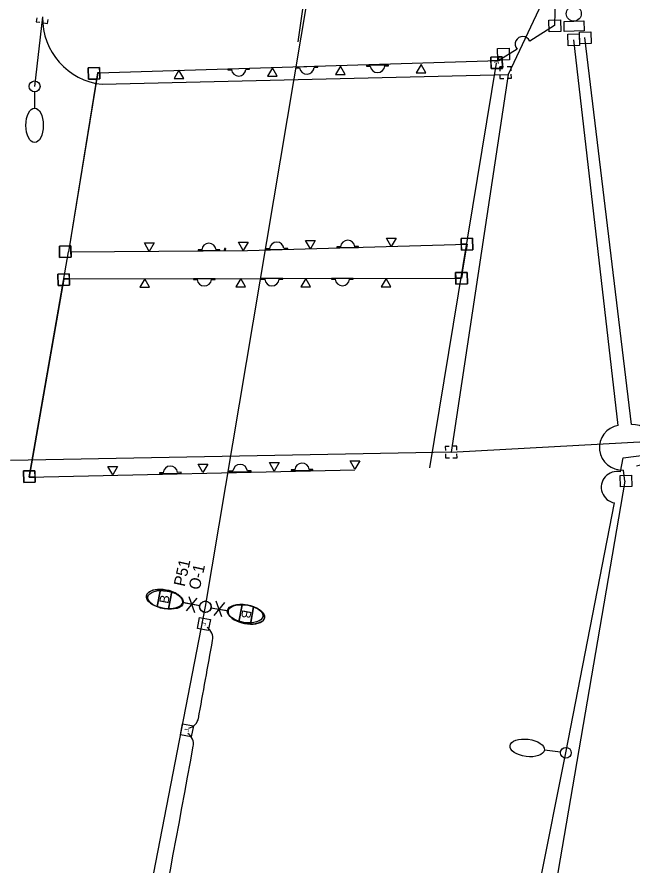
# Model space of a CAD drawing. Extents: x 925407 to 930994, y 604905 to 637063.
# Drawn here: x 930469.3 to 930738.1, y 618416 to 618786.5 of the extents above; entities that cross this region are included whole.
import ezdxf

# ---------------------------------------------------------------- set-up
doc = ezdxf.new("R2010")
doc.units = 0
for name, color, linetype in [('ActivePointCell_dp', 7, 'Continuous'), ('Conduit', 7, 'Continuous'), ('ConduitDB', 7, 'Continuous'), ('ConduitJB', 7, 'Continuous'), ('ConduitOT', 7, 'Continuous'), ('LightingMisc', 7, 'Continuous'), ('LiteCond_ep', 7, 'Continuous'), ('LoadCenter', 7, 'Continuous'), ('Miscellaneous2', 7, 'Continuous'), ('Miscellaneous9', 7, 'Continuous'), ('PoleLight', 7, 'Continuous'), ('PoleLight_ep', 7, 'Continuous'), ('PullBox', 7, 'Continuous'), ('SoilBoxes_px', 7, 'Continuous')]:
    doc.layers.add(name, color=color, linetype=linetype)

msp = doc.modelspace()

# ---------------------------------------------------------------- linework, layer by layer
for points in [[(930560.46, 618685.29), (930560.02, 618685.33), (930559.93, 618684.52), (930560.37, 618684.47)], [(930560.37, 618684.47), (930560.46, 618685.29), (930560.46, 618685.29), (930560.37, 618684.47)]]:
    msp.add_lwpolyline(points, close=True)
at = {"layer": 'ActivePointCell_dp'}
msp.add_line((930618.39, 618963.87), (930592.1, 618775.67), dxfattribs=at)
at = {"layer": 'Conduit'}
for p, q in [((930720.15, 618838.16), (930683.96, 618761.37)), ((930480.53, 618786.47), (930477.05, 618756.15)), ((930506.57, 618757.04), (930683.96, 618761.37)), ((930683.96, 618761.37), (930659.01, 618596.36)), ((930659.01, 618596.36), (930827.84, 618605.52)), ((930734.26, 618593.79), (930822.57, 618605.19)), ((930659.01, 618596.36), (930466.5, 618592.68)), ((930733.07, 618587.68), (930734.26, 618593.79)), ((930709.17, 618464.99), (930730.45, 618574.22)), ((930671.82, 618277.75), (930709.17, 618464.96))]:
    msp.add_line(p, q, dxfattribs=at)
for centre, radius, start, end in [((930509.6, 618785.96), 29.08, 178.9945, 264.0152), ((930731.51, 618581), 6.87, 76.85, 261.1041)]:
    msp.add_arc(centre, radius, start, end, dxfattribs=at)
at = {"layer": 'ConduitDB'}
for p, q in [((930737.86, 618608.37), (930717.5, 618777.55)), ((930732.07, 618608.04), (930712.58, 618776.48)), ((930734.88, 618583.7), (930734.32, 618588.54))]:
    msp.add_line(p, q, dxfattribs=at)
for centre, radius, start, end in [((930733.68, 618598.35), 9.83, 99.4413, 273.7548), ((930738.6, 618599.34), 9.06, 279.0871, 94.6401)]:
    msp.add_arc(centre, radius, start, end, dxfattribs=at)
at = {"layer": 'ConduitJB'}
for p, q in [((930504.59, 618762.1), (930679.89, 618767.39)), ((930679.64, 618767.67), (930680.88, 618767.71)), ((930492.01, 618683.91), (930504.59, 618762.1)), ((930492.54, 618683.83), (930570.06, 618684.49)), ((930570.13, 618684.45), (930665.97, 618687.21)), ((930663.56, 618672.32), (930665.97, 618687.21)), ((930489.8, 618672), (930474.65, 618585.35)), ((930489.8, 618672), (930663.56, 618672.32)), ((930474.65, 618585.35), (930617, 618588.64))]:
    msp.add_line(p, q, dxfattribs=at)
at = {"layer": 'ConduitOT'}
for p, q in [((930704.72, 618801.33), (930704.15, 618782.79)), ((930704.15, 618782.79), (930693.37, 618775.96)), ((930687.86, 618772.46), (930679.94, 618767.43))]:
    msp.add_line(p, q, dxfattribs=at)
msp.add_lwpolyline([(930734.88, 618583.7), (930694.71, 618348.94)], dxfattribs=at)
for centre, radius, start, end in [((930690.34, 618774.64), 3.3, 23.4064, 221.404), ((930549.39, 618515.13), 5.5, 349.5299, 57.2394), ((919236.07, 620547.92), 11500, 349.639964, 349.813549), ((930543.25, 618481.17), 5.5, 281.9557, 349.5925), ((930540.98, 618468.82), 5.5, 349.5299, 57.2394), ((919236.07, 620547.92), 11500, 348.486539, 349.579184)]:
    msp.add_arc(centre, radius, start, end, dxfattribs=at)
at = {"layer": 'LightingMisc'}
for p, q in [((930570.94, 618763.93), (930561.42, 618763.72)), ((930561.42, 618763.72), (930561.43, 618763.41)), ((930561.43, 618763.41), (930563.03, 618763.44)), ((930569.34, 618763.58), (930570.95, 618763.62)), ((930570.95, 618763.62), (930570.94, 618763.93)), ((930600.75, 618764.81), (930591.23, 618764.54)), ((930591.23, 618764.54), (930591.24, 618764.22)), ((930591.24, 618764.22), (930592.84, 618764.27)), ((930599.15, 618764.44), (930600.76, 618764.49)), ((930600.76, 618764.49), (930600.75, 618764.81)), ((930631.62, 618765.42), (930622.1, 618765.25)), ((930622.1, 618765.25), (930622.1, 618764.93)), ((930622.1, 618764.93), (930623.71, 618764.96)), ((930630.02, 618765.07), (930631.62, 618765.1)), ((930631.62, 618765.1), (930631.62, 618765.42)), ((930550.03, 618684.73), (930548.43, 618684.72)), ((930548.43, 618684.72), (930548.43, 618684.4)), ((930548.43, 618684.4), (930557.95, 618684.48)), ((930557.95, 618684.8), (930556.35, 618684.79)), ((930557.95, 618684.48), (930557.95, 618684.8)), ((930579.69, 618685.21), (930578.09, 618685.19)), ((930578.09, 618685.19), (930578.09, 618684.87)), ((930578.09, 618684.87), (930587.61, 618684.96)), ((930587.61, 618685.27), (930586.01, 618685.26)), ((930587.61, 618684.96), (930587.61, 618685.27)), ((930610.71, 618686.06), (930609.11, 618686.05)), ((930609.11, 618686.05), (930609.11, 618685.73)), ((930609.11, 618685.73), (930618.63, 618685.81)), ((930618.63, 618686.13), (930617.03, 618686.12)), ((930618.63, 618685.81), (930618.63, 618686.13)), ((930555.92, 618672.12), (930546.4, 618672.11)), ((930546.4, 618672.11), (930546.4, 618671.79)), ((930546.4, 618671.79), (930548, 618671.79)), ((930554.32, 618671.8), (930555.92, 618671.81)), ((930555.92, 618671.81), (930555.92, 618672.12)), ((930585.51, 618672.18), (930575.99, 618672.16)), ((930575.99, 618672.16), (930575.99, 618671.85)), ((930575.99, 618671.85), (930577.6, 618671.85)), ((930583.91, 618671.86), (930585.51, 618671.86)), ((930585.51, 618671.86), (930585.51, 618672.18)), ((930616.28, 618672.23), (930606.76, 618672.22)), ((930606.76, 618672.22), (930606.76, 618671.9)), ((930606.76, 618671.9), (930608.36, 618671.9)), ((930614.68, 618671.91), (930616.28, 618671.92)), ((930616.28, 618671.92), (930616.28, 618672.23)), ((930563.7, 618588.11), (930562.1, 618588.1)), ((930562.1, 618588.1), (930562.1, 618587.78)), ((930571.62, 618588.15), (930570.01, 618588.14)), ((930571.62, 618587.84), (930571.62, 618588.15)), ((930590.69, 618588.62), (930589.08, 618588.58)), ((930589.08, 618588.58), (930589.09, 618588.26)), ((930589.09, 618588.26), (930598.61, 618588.47)), ((930598.6, 618588.79), (930597, 618588.75)), ((930598.61, 618588.47), (930598.6, 618588.79)), ((930533.19, 618587.35), (930531.58, 618587.31)), ((930531.58, 618587.31), (930531.59, 618586.99)), ((930531.59, 618586.99), (930541.11, 618587.21)), ((930541.1, 618587.53), (930539.5, 618587.49)), ((930541.11, 618587.21), (930541.1, 618587.53)), ((930562.1, 618587.78), (930571.62, 618587.84))]:
    msp.add_line(p, q, dxfattribs=at)
for points in [[(930537.99, 618759.56), (930542.21, 618759.56), (930540.1, 618763.21)], [(930578.83, 618760.56), (930583.05, 618760.56), (930580.94, 618764.22)], [(930608.56, 618761.33), (930612.78, 618761.33), (930610.67, 618764.99)], [(930643.82, 618762.06), (930648.04, 618762.06), (930645.93, 618765.72)], [(930595.47, 618688.84), (930599.68, 618688.84), (930597.58, 618685.19)], [(930630.77, 618689.86), (930634.99, 618689.86), (930632.88, 618686.2)], [(930525, 618687.72), (930529.22, 618687.72), (930527.11, 618684.07)], [(930566.09, 618688.07), (930570.31, 618688.07), (930568.2, 618684.42)], [(930523.08, 618668.42), (930527.3, 618668.42), (930525.19, 618672.08)], [(930564.97, 618668.54), (930569.19, 618668.54), (930567.08, 618672.19)], [(930593.38, 618668.52), (930597.6, 618668.52), (930595.49, 618672.17)], [(930628.53, 618668.58), (930632.75, 618668.58), (930630.64, 618672.24)], [(930614.88, 618592.56), (930619.1, 618592.56), (930616.99, 618588.91)], [(930509.05, 618590.08), (930513.27, 618590.08), (930511.16, 618586.43)], [(930548.44, 618591.08), (930552.66, 618591.08), (930550.55, 618587.42)], [(930579.61, 618591.75), (930583.83, 618591.75), (930581.72, 618588.09)]]:
    msp.add_lwpolyline(points, close=True, dxfattribs=at)
for centre, start, end in [((930566.18, 618763.83), 186.9974, 355.519), ((930595.99, 618764.67), 187.3392, 355.8608), ((930626.86, 618765.33), 186.7733, 355.2948), ((930613.87, 618685.77), 6.2311, 174.7527), ((930553.19, 618684.44), 6.2264, 174.748), ((930582.85, 618684.92), 6.2264, 174.748), ((930551.16, 618672.12), 185.8184, 354.34), ((930580.75, 618672.17), 185.8184, 354.34), ((930611.52, 618672.23), 185.8184, 354.34), ((930536.35, 618587.1), 7.061, 175.5826), ((930566.86, 618587.81), 6.0485, 174.5701), ((930593.85, 618588.37), 6.9778, 175.4994)]:
    msp.add_arc(centre, 3.17, start, end, dxfattribs=at)
at = {"layer": 'LiteCond_ep'}
for p, q in [((930551.66, 618528.87), (930598.48, 618807.43)), ((930679.57, 618768.98), (930676.35, 618768.9)), ((930676.35, 618768.9), (930676.39, 618767.29)), ((930676.39, 618767.29), (930679.48, 618767.38)), ((930676.39, 618767.29), (930676.48, 618763.9)), ((930679.64, 618767.67), (930679.48, 618767.38)), ((930679.48, 618767.38), (930679.65, 618767.39)), ((930679.48, 618767.38), (930679.89, 618767.39)), ((930681.35, 618769.02), (930679.57, 618768.98)), ((930681.35, 618769.02), (930679.57, 618768.98)), ((930679.64, 618767.67), (930679.57, 618768.98)), ((930679.57, 618768.98), (930679.64, 618767.67)), ((930679.83, 618767.71), (930679.57, 618768.98)), ((930679.83, 618767.68), (930679.64, 618767.67)), ((930679.64, 618767.67), (930679.83, 618767.68)), ((930679.83, 618767.68), (930679.83, 618767.71)), ((930679.84, 618767.66), (930679.83, 618767.68)), ((930680.33, 618767.67), (930679.84, 618767.66)), ((930680.8, 618767.68), (930679.89, 618767.39)), ((930679.89, 618767.39), (930680.33, 618767.67)), ((930680.33, 618767.67), (930679.89, 618767.39)), ((930679.89, 618767.39), (930680.37, 618767.55)), ((930680.72, 618767.7), (930680.33, 618767.67)), ((930680.33, 618767.67), (930680.72, 618767.7)), ((930680.36, 618767.69), (930680.33, 618767.67)), ((930680.73, 618767.93), (930680.36, 618767.69)), ((930680.73, 618767.93), (930680.36, 618767.69)), ((930680.36, 618767.69), (930680.88, 618767.71)), ((930680.88, 618767.71), (930680.36, 618767.69)), ((930680.36, 618767.69), (930680.72, 618767.7)), ((930680.72, 618767.7), (930680.36, 618767.69)), ((930680.36, 618767.69), (930680.72, 618767.7)), ((930680.36, 618767.69), (930680.36, 618767.69)), ((930680.37, 618767.55), (930680.8, 618767.68)), ((930680.72, 618767.7), (930680.88, 618767.71)), ((930680.72, 618767.7), (930680.85, 618767.71)), ((930680.85, 618767.71), (930680.72, 618767.7)), ((930680.8, 618767.7), (930680.72, 618767.7)), ((930681.37, 618768.33), (930680.73, 618767.93)), ((930681.37, 618768.33), (930680.73, 618767.93)), ((930680.8, 618767.68), (930681.39, 618767.7)), ((930680.85, 618767.7), (930680.8, 618767.68)), ((930680.8, 618767.68), (930680.85, 618767.7)), ((930680.85, 618767.7), (930680.8, 618767.7)), ((930680.85, 618767.71), (930680.88, 618767.71)), ((930680.88, 618767.71), (930681.06, 618767.7)), ((930680.88, 618767.71), (930681.06, 618767.7)), ((930681.06, 618767.7), (930681.38, 618767.71)), ((930681.39, 618767.7), (930681.06, 618767.7)), ((930681.06, 618767.7), (930681.39, 618767.7)), ((930681.37, 618768.33), (930681.35, 618769.02)), ((930681.37, 618768.33), (930681.35, 618769.02)), ((930681.38, 618767.71), (930681.37, 618768.33)), ((930681.39, 618767.7), (930681.37, 618768.33)), ((930681.46, 618764.62), (930681.39, 618767.7)), ((930505.44, 618764.38), (930500.44, 618764.25)), ((930500.44, 618764.25), (930500.57, 618759.25)), ((930505.5, 618762.12), (930505.44, 618764.38)), ((930676.48, 618763.9), (930680.3, 618764)), ((930680.3, 618764.61), (930681.46, 618764.62)), ((930681.46, 618764.62), (930680.3, 618764.61)), ((930680.3, 618764), (930680.3, 618764.61)), ((930680.3, 618764.61), (930680.3, 618764)), ((930680.3, 618764), (930681.41, 618764.02)), ((930681.48, 618764.1), (930681.46, 618764.62)), ((930500.57, 618759.25), (930504.15, 618759.34)), ((930504.15, 618759.34), (930504.59, 618762.1)), ((930504.59, 618762.1), (930504.15, 618759.34)), ((930504.15, 618759.34), (930505.57, 618759.38)), ((930504.59, 618762.1), (930505.5, 618762.12)), ((930505.5, 618762.12), (930504.59, 618762.1)), ((930505.57, 618759.38), (930505.5, 618762.12)), ((930668.4, 618689.77), (930663.4, 618689.64)), ((930663.4, 618689.64), (930663.47, 618687.14)), ((930668.53, 618684.77), (930668.4, 618689.77)), ((930487.84, 618686.33), (930487.97, 618681.33)), ((930665.97, 618687.21), (930663.47, 618687.14)), ((930663.47, 618687.14), (930665.97, 618687.21)), ((930663.47, 618687.14), (930663.53, 618684.65)), ((930663.53, 618684.65), (930665.56, 618684.7)), ((930665.56, 618684.7), (930665.97, 618687.21)), ((930665.97, 618687.21), (930665.56, 618684.7)), ((930665.56, 618684.7), (930668.53, 618684.77)), ((930487.97, 618681.33), (930492.97, 618681.46)), ((930492.18, 618674.25), (930487.18, 618674.12)), ((930487.18, 618674.12), (930487.31, 618669.13)), ((930492.24, 618672.01), (930492.18, 618674.25)), ((930663.96, 618674.84), (930660.99, 618674.76)), ((930660.99, 618674.76), (930661.06, 618672.32)), ((930663.96, 618674.84), (930663.56, 618672.32)), ((930663.56, 618672.32), (930663.96, 618674.84)), ((930665.99, 618674.89), (930663.96, 618674.84)), ((930666.12, 618669.89), (930665.99, 618674.89)), ((930489.31, 618669.18), (930489.8, 618672)), ((930489.8, 618672), (930489.31, 618669.18)), ((930489.8, 618672), (930492.24, 618672.01)), ((930492.24, 618672.01), (930489.8, 618672)), ((930492.31, 618669.25), (930492.24, 618672.01)), ((930663.56, 618672.32), (930661.06, 618672.32)), ((930661.06, 618672.32), (930661.12, 618669.76)), ((930661.06, 618672.32), (930663.56, 618672.32)), ((930661.12, 618669.76), (930666.12, 618669.89)), ((930487.31, 618669.13), (930489.31, 618669.18)), ((930489.31, 618669.18), (930492.31, 618669.25)), ((930475.15, 618588.19), (930472.14, 618588.11)), ((930472.14, 618588.11), (930472.27, 618583.11)), ((930474.65, 618585.35), (930475.15, 618588.19)), ((930475.15, 618588.19), (930474.65, 618585.35)), ((930477.14, 618588.24), (930475.15, 618588.19)), ((930477.21, 618585.41), (930477.14, 618588.24)), ((930477.21, 618585.41), (930474.65, 618585.35)), ((930474.65, 618585.35), (930477.21, 618585.41)), ((930477.27, 618583.24), (930477.21, 618585.41)), ((930472.27, 618583.11), (930477.27, 618583.24)), ((930498.32, 618253.03), (930551.66, 618528.87))]:
    msp.add_line(p, q, dxfattribs=at)
for points in [[(930679.89, 618767.39), (930679.48, 618767.38), (930676.39, 618767.29)], [(930679.57, 618768.98), (930679.82, 618767.72), (930679.84, 618767.66)], [(930679.57, 618768.98), (930679.83, 618767.71), (930679.83, 618767.68)], [(930679.64, 618767.67), (930679.83, 618767.71)], [(930679.83, 618767.71), (930679.64, 618767.67)], [(930679.65, 618767.39), (930679.64, 618767.67)], [(930679.83, 618767.68), (930679.84, 618767.68), (930680.33, 618767.69), (930680.36, 618767.69)], [(930679.84, 618767.66), (930679.89, 618767.66), (930680.33, 618767.67)], [(930680.33, 618767.67), (930680.73, 618767.93), (930681.37, 618768.33)], [(930680.37, 618767.55), (930680.33, 618767.67)], [(930680.33, 618767.67), (930680.37, 618767.55)], [(930680.36, 618767.69), (930680.73, 618767.93), (930681.37, 618768.33)], [(930680.72, 618767.7), (930680.8, 618767.7), (930680.85, 618767.7)], [(930681.39, 618767.7), (930680.88, 618767.69), (930680.8, 618767.68)], [(930680.8, 618767.68), (930680.8, 618767.7)], [(930680.8, 618767.7), (930680.8, 618767.68)], [(930680.85, 618767.7), (930680.85, 618767.71)], [(930681.06, 618767.7), (930680.88, 618767.7), (930680.85, 618767.7)], [(930681.41, 618764.02), (930681.44, 618764.06), (930681.48, 618764.1)], [(930492.84, 618686.46), (930492.42, 618686.45), (930487.84, 618686.33)], [(930492.97, 618681.46), (930492.91, 618683.83), (930492.84, 618686.46)]]:
    msp.add_lwpolyline(points, dxfattribs=at)
at = {"layer": 'LoadCenter'}
for p, q in [((930708.36, 618784.5), (930717.09, 618784.73)), ((930708.47, 618780.14), (930708.36, 618784.5)), ((930717.09, 618784.73), (930717.2, 618780.36)), ((930717.2, 618780.36), (930708.47, 618780.14))]:
    msp.add_line(p, q, dxfattribs=at)
msp.add_circle((930712.64, 618787.89), 3.27, dxfattribs=at)
at = {"layer": 'Miscellaneous2'}
for p, q in [((930532, 618536.38), (930530.59, 618528.85)), ((930532, 618536.38), (930532, 618536.38)), ((930535.6, 618527.91), (930537.01, 618535.44)), ((930537.01, 618535.44), (930537.01, 618535.44)), ((930567.73, 618529.7), (930566.32, 618522.16)), ((930567.73, 618529.7), (930567.73, 618529.7)), ((930571.33, 618521.22), (930572.74, 618528.76)), ((930572.74, 618528.76), (930572.74, 618528.76))]:
    msp.add_line(p, q, dxfattribs=at)
for centre, start_param, end_param in [((930533.8, 618532.15), 1.249648, 1.891946), ((930533.8, 618532.15), 4.391241, 4.391271), ((930533.8, 618532.15), 4.391271, 5.033538), ((930569.53, 618525.46), 1.249648, 1.891946), ((930569.53, 618525.46), 4.391241, 4.391271), ((930569.53, 618525.46), 4.391271, 5.033538)]:
    msp.add_ellipse(centre, major_axis=(7.94, -1.49), ratio=0.5, start_param=start_param, end_param=end_param, dxfattribs=at)
at = {"layer": 'PoleLight'}
for p, q in [((930530.59, 618528.85), (930532, 618536.38)), ((930537.01, 618535.44), (930535.6, 618527.91)), ((930549.18, 618529.27), (930541.74, 618530.66)), ((930566.32, 618522.16), (930567.73, 618529.7)), ((930554.15, 618528.34), (930561.59, 618526.95)), ((930572.74, 618528.76), (930571.33, 618521.22))]:
    msp.add_line(p, q, dxfattribs=at)
msp.add_circle((930551.67, 618528.8), 2.52, dxfattribs=at)
msp.add_circle((930551.67, 618528.8), 2.52, dxfattribs=at)
for centre in [(930533.8, 618532.15), (930569.53, 618525.46)]:
    msp.add_ellipse(centre, major_axis=(7.94, -1.49), ratio=0.5, dxfattribs=at)
for centre, start_param, end_param in [((930533.8, 618532.15), 1.891945, 4.391241), ((930533.8, 618532.15), 0.847605, 1.249648), ((930533.8, 618532.15), 0, 0.847605), ((930533.8, 618532.15), 5.033538, 6.283185), ((930569.53, 618525.46), 1.891945, 4.391241), ((930569.53, 618525.46), 0.847605, 1.249648), ((930569.53, 618525.46), 0, 0.847605), ((930569.53, 618525.46), 5.033538, 6.283185)]:
    msp.add_ellipse(centre, major_axis=(7.94, -1.49), ratio=0.5, start_param=start_param, end_param=end_param, dxfattribs=at)
at = {"layer": 'PoleLight_ep'}
for p, q in [((930477.05, 618753.78), (930477.05, 618746.69)), ((930543.35, 618526.95), (930548.04, 618532.61)), ((930544.42, 618533.23), (930546.97, 618526.33)), ((930549.25, 618529.22), (930542, 618530.45)), ((930559.98, 618530.65), (930555.29, 618525)), ((930558.91, 618524.38), (930556.36, 618531.27)), ((930554.08, 618528.39), (930561.33, 618527.16)), ((930706.82, 618465.29), (930699.78, 618466.18))]:
    msp.add_line(p, q, dxfattribs=at)
for centre, radius in [((930477.05, 618756.15), 2.37), ((930551.67, 618528.8), 2.45), ((930709.17, 618464.99), 2.37)]:
    msp.add_circle(centre, radius, dxfattribs=at)
for centre, major_axis in [((930477.04, 618739.12), (0, -7.57)), ((930534.28, 618531.77), (-7.73, 1.32)), ((930569.05, 618525.84), (7.73, -1.32)), ((930692.27, 618467.14), (-7.51, 0.96))]:
    msp.add_ellipse(centre, major_axis=major_axis, ratio=0.5, dxfattribs=at)
at = {"layer": 'PullBox'}
for p, q in [((930701.79, 618785.03), (930706.79, 618785.16)), ((930701.92, 618780.03), (930701.79, 618785.03)), ((930706.79, 618785.16), (930706.92, 618780.16)), ((930706.92, 618780.16), (930701.92, 618780.03)), ((930710.02, 618778.92), (930715.02, 618779.05)), ((930710.15, 618773.92), (930710.02, 618778.92)), ((930715.02, 618779.05), (930715.15, 618774.05)), ((930715.14, 618779.78), (930720.14, 618779.91)), ((930715.27, 618774.79), (930715.14, 618779.78)), ((930720.14, 618779.91), (930720.27, 618774.91)), ((930715.15, 618774.05), (930710.15, 618773.92)), ((930720.27, 618774.91), (930715.27, 618774.79)), ((930679.34, 618772.65), (930684.34, 618772.78)), ((930679.47, 618767.65), (930679.34, 618772.65)), ((930684.34, 618772.78), (930684.47, 618767.78)), ((930676.35, 618768.9), (930681.35, 618769.02)), ((930676.48, 618763.9), (930676.35, 618768.9)), ((930684.47, 618767.78), (930679.47, 618767.65)), ((930681.35, 618769.02), (930681.48, 618764.03)), ((930500.44, 618764.25), (930505.44, 618764.38)), ((930500.57, 618759.25), (930500.44, 618764.25)), ((930505.44, 618764.38), (930505.57, 618759.38)), ((930681.48, 618764.03), (930676.48, 618763.9)), ((930505.57, 618759.38), (930500.57, 618759.25)), ((930663.4, 618689.64), (930668.4, 618689.77)), ((930663.53, 618684.65), (930663.4, 618689.64)), ((930668.4, 618689.77), (930668.53, 618684.77)), ((930487.84, 618686.33), (930492.84, 618686.46)), ((930487.97, 618681.33), (930487.84, 618686.33)), ((930492.84, 618686.46), (930492.97, 618681.46)), ((930668.53, 618684.77), (930663.53, 618684.65)), ((930492.97, 618681.46), (930487.97, 618681.33)), ((930487.18, 618674.12), (930492.18, 618674.25)), ((930487.31, 618669.13), (930487.18, 618674.12)), ((930492.18, 618674.25), (930492.31, 618669.25)), ((930660.99, 618674.76), (930665.99, 618674.89)), ((930661.12, 618669.76), (930660.99, 618674.76)), ((930665.99, 618674.89), (930666.12, 618669.89)), ((930666.12, 618669.89), (930661.12, 618669.76)), ((930492.31, 618669.25), (930487.31, 618669.13)), ((930472.14, 618588.11), (930477.14, 618588.24)), ((930472.27, 618583.11), (930472.14, 618588.11)), ((930477.14, 618588.24), (930477.27, 618583.24)), ((930732.9, 618586.16), (930737.9, 618586.29)), ((930733.03, 618581.16), (930732.9, 618586.16)), ((930737.9, 618586.29), (930738.03, 618581.29)), ((930477.27, 618583.24), (930472.27, 618583.11)), ((930738.03, 618581.29), (930733.03, 618581.16)), ((930548.17, 618519.35), (930549.06, 618524.11)), ((930549.06, 618524.11), (930553.82, 618523.22)), ((930553.82, 618523.22), (930552.93, 618518.46)), ((930552.93, 618518.46), (930548.17, 618519.35)), ((930540.73, 618472.9), (930541.62, 618477.67)), ((930541.62, 618477.67), (930546.39, 618476.78)), ((930546.39, 618476.78), (930545.5, 618472.01)), ((930545.5, 618472.01), (930540.73, 618472.9))]:
    msp.add_line(p, q, dxfattribs=at)
for points in [[(930477.99, 618786.12), (930477.7, 618784.41), (930479.36, 618784.14)], [(930482.64, 618783.6), (930482.92, 618785.31)], [(930480.89, 618783.89), (930482.64, 618783.6)], [(930681.97, 618764.63), (930680.3, 618764.61), (930680.32, 618762.85)], [(930685.32, 618762.91), (930685.3, 618764.67), (930683.52, 618764.65)], [(930680.34, 618761.35), (930680.36, 618759.61), (930682.04, 618759.64)], [(930683.59, 618759.66), (930685.36, 618759.68)], [(930685.36, 618759.68), (930685.34, 618761.41)], [(930658.18, 618598.85), (930656.5, 618598.82), (930656.54, 618597.05)], [(930656.57, 618595.55), (930656.61, 618593.82), (930658.29, 618593.86)], [(930661.54, 618597.16), (930661.5, 618598.92), (930659.73, 618598.89)], [(930661.61, 618593.93), (930661.57, 618595.66)], [(930659.84, 618593.89), (930661.61, 618593.93)]]:
    msp.add_lwpolyline(points, dxfattribs=at)
at = {"layer": 'SoilBoxes_px'}
for p, q in [((930678.7, 618766.31), (930649.59, 618589.52)), ((930678.7, 618766.31), (930649.59, 618589.52)), ((930491.97, 618683.92), (930504.8, 618762.38)), ((930474.63, 618585.36), (930491.8, 618683.91))]:
    msp.add_line(p, q, dxfattribs=at)

# ---------------------------------------------------------------- texts
at = {"layer": 'ActivePointCell_dp'}
for s, p in [('P51', (930542.6, 618537.36)), ('O-1', (930549.14, 618535.91))]:
    msp.add_text(s, height=5, rotation=77.5026, dxfattribs=at).set_placement(p)
at = {"layer": 'Miscellaneous9'}
for rotation, p in [(79.4013, (930535.46, 618529.94)), (259.4013, (930567.87, 618527.67))]:
    msp.add_text('B', height=4.08, rotation=rotation, dxfattribs=at).set_placement(p)
at = {"layer": 'PullBox'}
for height, rotation, p in [(2, 91.4756, (930679.93, 618765.81)), (1.94, 79.4065, (930551.83, 618520.46)), (1.94, 79.4065, (930544.39, 618474.02))]:
    msp.add_text('J', height=height, rotation=rotation, dxfattribs=at).set_placement(p)

doc.saveas('drawing.dxf')
